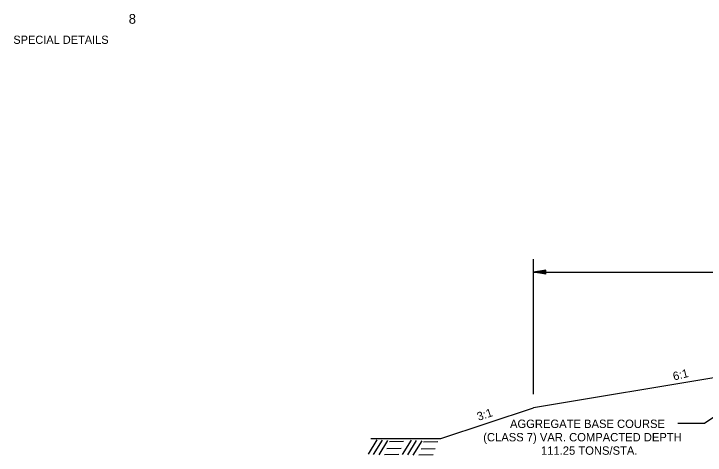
# Model space of a CAD drawing. Extents: x 634177 to 635904, y 289936 to 290970.
# Drawn here: x 635771.45 to 635820.98, y 290604.72 to 290636.37 of the extents above; entities that cross this region are included whole.
import ezdxf

# ---------------------------------------------------------------- set-up
doc = ezdxf.new("R2010")
doc.units = 0
for name, color, linetype in [('3', 7, 'Continuous'), ('Default', 7, 'Continuous'), ('R_Border', 7, 'Continuous'), ('R_Border Notes', 7, 'Continuous')]:
    doc.layers.add(name, color=color, linetype=linetype)

msp = doc.modelspace()

# ---------------------------------------------------------------- linework, layer by layer
at = {"layer": '3'}
for p, q in [((635796.854, 290604.804), (635797.494, 290605.829)), ((635797.214, 290604.775), (635797.854, 290605.8)), ((635797.616, 290604.748), (635798.256, 290605.772)), ((635798.359, 290605.701), (635799.376, 290605.728)), ((635799.309, 290604.782), (635799.95, 290605.806)), ((635799.669, 290604.753), (635800.309, 290605.777)), ((635800.071, 290604.725), (635800.711, 290605.749)), ((635798.175, 290605.21), (635799.193, 290605.237)), ((635800.631, 290605.187), (635801.648, 290605.214)), ((635800.814, 290605.678), (635801.831, 290605.705)), ((635798.015, 290604.778), (635799.033, 290604.806)), ((635800.47, 290604.755), (635801.488, 290604.783))]:
    msp.add_line(p, q, dxfattribs=at)
at = {"layer": 'Default'}
for p, q in [((635808.678, 290609.107), (635808.678, 290618.787)), ((635809.578, 290617.981), (635808.678, 290617.846)), ((635809.578, 290617.711), (635808.678, 290617.846)), ((635808.678, 290617.846), (635838.678, 290617.846)), ((635809.578, 290617.959), (635808.828, 290617.846)), ((635809.578, 290617.734), (635808.828, 290617.846)), ((635809.578, 290617.936), (635808.983, 290617.846)), ((635809.578, 290617.756), (635808.983, 290617.846)), ((635809.578, 290617.913), (635809.132, 290617.846)), ((635809.578, 290617.779), (635809.132, 290617.846)), ((635809.578, 290617.891), (635809.285, 290617.846)), ((635809.578, 290617.802), (635809.285, 290617.846)), ((635809.578, 290617.867), (635809.436, 290617.846)), ((635809.578, 290617.825), (635809.436, 290617.846)), ((635809.578, 290617.711), (635809.578, 290617.981)), ((635830.678, 290611.794), (635808.678, 290608.128)), ((635802.037, 290605.914), (635808.678, 290608.128)), ((635797.037, 290605.914), (635802.037, 290605.914))]:
    msp.add_line(p, q, dxfattribs=at)
for points in [[(635826.132, 290610.504), (635820.929, 290606.991)], [(635820.929, 290606.991), (635819.012, 290606.991)]]:
    msp.add_lwpolyline(points, dxfattribs=at)

# ---------------------------------------------------------------- texts
for s, rotation, p in [('6:1', 14.0362, (635818.751, 290610.073)), ('3:1', 18.4349, (635804.752, 290607.185))]:
    msp.add_text(s, height=0.6, rotation=rotation, dxfattribs=at).set_placement(p)
for s, p in [('AGGREGATE BASE COURSE', (635807, 290606.675)), ('(CLASS 7) VAR. COMPACTED DEPTH', (635805.082, 290605.715)), ('111.25 TONS/STA.', (635809.221, 290604.755))]:
    msp.add_text(s, height=0.6, dxfattribs=at).set_placement(p)
at = {"layer": 'R_Border'}
msp.add_text('8', height=0.7, dxfattribs=at).set_placement((635779.684, 290635.663))
at = {"layer": 'R_Border Notes'}
msp.add_text('SPECIAL DETAILS', height=0.58876, dxfattribs=at).set_placement((635771.416, 290634.219))

doc.saveas('drawing.dxf')
